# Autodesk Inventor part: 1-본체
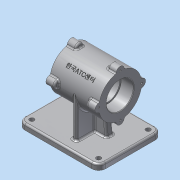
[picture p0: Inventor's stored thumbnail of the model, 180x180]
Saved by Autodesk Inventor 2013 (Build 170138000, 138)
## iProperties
Created: 2015-12
Part Number: 1-본체
Material: 알루미늄 6061
Document SubType Name: Modeling
Designer: ST1
Density: 2.71 g/cm^3
Mass: 1167.31 g
Surface Area: 816.82 cm^2
Volume: 430.742 cm^3
Author: ST1
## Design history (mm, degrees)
sketch "스케치1"
  geometry: L1 (0, 0)-(85, 0); L2 (0, 23.5)-(22, 23.5); L3 (22, 23.5)-(22, 21); L4 (22, 21)-(63, 21); L5 (63, 21)-(63, 23.5); L6 (63, 23.5)-(85, 23.5); L7 (0, 23.5)-(0, 37); L8 (0, 37)-(85, 37); L9 (85, 37)-(85, 23.5)
  constraints: 18 end point, 6 perpendicular, 2 parallel, 2 vertical alignment, 1 horizontal, 1 horizontal alignment
  dimensions: "d0" = 85 distance of L1.start L1.end; "d1" = 47 diameter of L2 L1; "d2" = 22 distance of L2.start L2.end; "d3" = 42 diameter of L4 L1; "d4" = 41 distance of L3.end L4.end; "d5" = 74 diameter of L8 L1
revolve "회전1" sketch "스케치1" stored, may be unused: angle "d6" = 90 deg
sketch "스케치2"
  geometry: C1 r 23.5 at (0, 0) reference; C2 r 7 at (0, 37); C3 r 7 at (37, 0); C4 r 7 at (-37, 0); C5 r 7 at (0, -37); A1 r 37 centre (0, 0) between (0, 37) and (37, 0) reference
  constraints: 4 centre point, 4 point on circle, 3 equal radius, 2 horizontal alignment, 2 vertical alignment
  dimensions: "d7" = 14 diameter of C2
extrude "돌출1" join sketch "스케치2" distance "d9" = 15; taper "d10" = 0 deg
node "작업 평면1"
sketch "스케치3"
  geometry: A1 r 7 centre (0, 0) between (-0.662, -6.969) and (-0.662, 6.969) reference; A2 r 7 centre (-37, 37) between (-30.031, 36.338) and (-43.969, 36.338) reference; A3 r 7 centre (-74, 0) between (-73.338, 6.969) and (-73.338, -6.969) reference; A4 r 7 centre (-37, -37) between (-43.969, -36.338) and (-30.031, -36.338) reference; 4 further points
  constraints: 4 coincident
hole "구멍1" sketch "스케치3" at (-37, 37), (0, 0), (-74, 0), (-37, -37) diameter "d11" = 3.242; stored, may be unused: countersink angle "d15" = 90 deg, drill point angle "d17" = 118 deg; dims "d12" = 9, "d13" = 4, "d14" = 2, "d16" = 11
fillet "모깎기1" dims "d18" = 0.3
chamfer "모따기1" distance "d19" = 1; stored, may be unused: second distance "d20" = 2, angle "d21" = 45 deg
fillet "모깎기2" dims "d22" = 3
sketch "스케치4"
  geometry: L1 (-37, 0)-(-79.773, 42.773); L2 (-37, 0)-(-99.297, 0); C1 r 1.621 at (-37, -37) reference; C2 r 1.621 at (0, 0) reference; C3 r 1.621 at (-37, 37) reference; C4 r 1.621 at (-74, 0) reference; C5 r 24.5 at (-37, 0) reference; A1 r 3 centre (-75.77, -9.842) between (-72.862, -9.104) and (-75.239, -6.889) reference; A2 r 7 centre (-74, 0) between (-75.239, 6.889) and (-75.239, -6.889) reference; A3 r 3 centre (-75.77, 9.842) between (-75.239, 6.889) and (-72.862, 9.104) reference; A4 r 37 centre (-37, 0) between (-46.104, 35.862) and (-72.862, 9.104) reference; A5 r 3 centre (-46.842, 38.77) between (-46.104, 35.862) and (-43.889, 38.239) reference; A6 r 7 centre (-37, 37) between (-30.111, 38.239) and (-43.889, 38.239) reference; A7 r 3 centre (-27.158, 38.77) between (-30.111, 38.239) and (-27.896, 35.862) reference; A8 r 37 centre (-37, 0) between (-1.138, 9.104) and (-27.896, 35.862) reference; A9 r 3 centre (1.77, 9.842) between (-1.138, 9.104) and (1.239, 6.889) reference; A10 r 7 centre (0, 0) between (1.239, -6.889) and (1.239, 6.889) reference; A11 r 3 centre (1.77, -9.842) between (1.239, -6.889) and (-1.138, -9.104) reference; A12 r 37 centre (-37, 0) between (-27.896, -35.862) and (-1.138, -9.104) reference; A13 r 3 centre (-27.158, -38.77) between (-27.896, -35.862) and (-30.111, -38.239) reference; A14 r 7 centre (-37, -37) between (-43.889, -38.239) and (-30.111, -38.239) reference; A15 r 3 centre (-46.842, -38.77) between (-43.889, -38.239) and (-46.104, -35.862) reference; A16 r 37 centre (-37, 0) between (-72.862, -9.104) and (-46.104, -35.862) reference; 1 further point
  constraints: 4 end point, 1 horizontal
  dimensions: "d23" = 45 deg angle of L2 L1
  node "투영된 루프1"
node "작업 평면2"
sketch "스케치5"
  geometry: L1 (-42.5, 18.921)-(-42.5, -18.921) reference; 2 further points
  constraints: 1 horizontal alignment, 1 other
  dimensions: "d24" = 42.5 distance from line of point (0, 0) L1
feature "엠보싱1" sketch "스케치5" dims "d0" = 85, "d1" = 47, "d2" = 22, "d3" = 42, "d4" = 41, "d5" = 74, "d25" = 0.5, "d26" = 0
node "작업 평면3"
sketch "스케치6"
  geometry: L1 (-17.5, 55)-(122.5, 55); L2 (122.5, 55)-(122.5, -55); L3 (122.5, -55)-(-17.5, -55); L4 (-17.5, -55)-(-17.5, 55); L5 (18, 37)-(67, 37) reference; L6 (0, 9.104)-(0, 35.862) reference; 3 further points
  constraints: 8 end point, 2 midpoint, 2 parallel, 1 horizontal, 1 horizontal alignment, 1 perpendicular
  dimensions: "d28" = 110 distance of L1.end L2.end; "d30" = 140 distance of L1.start L1.end; "d46" = 80 distance from line of L2 point (42.5, 37)
extrude "돌출2" join sketch "스케치6" distance "d31" = 10; taper "d32" = 0 deg
fillet "모깎기3" dims "d33" = 12
sketch "스케치7"
  geometry: C1 r 4 at (-5.5, 43); C2 r 4 at (110.5, 43); C3 r 4 at (110.5, -43); C4 r 4 at (-5.5, -43); A1 r 12 centre (110.5, -43) between (110.5, -55) and (122.5, -43) reference; A2 r 12 centre (110.5, 43) between (122.5, 43) and (110.5, 55) reference; A3 r 12 centre (-5.5, 43) between (-5.5, 55) and (-17.5, 43) reference; A4 r 12 centre (-5.5, -43) between (-17.5, -43) and (-5.5, -55) reference; 1 further point
  constraints: 4 centre point, 4 coincident, 3 equal radius
  dimensions: "d34" = 8 diameter of C1
extrude "돌출3" cut sketch "스케치7" distance "d36" = 10; taper "d37" = 0 deg
sketch "스케치8"
  geometry: L1 (122.5, -43)-(122.5, 43) reference; L2 (-5.5, -55)-(110.5, -55) reference; L3 (56.5, -37)-(48.5, -37); L4 (48.5, -37)-(48.5, 37); L5 (48.5, 37)-(56.5, 37); L6 (56.5, 37)-(56.5, -37); 5 further points
  constraints: 8 end point, 4 midpoint, 2 parallel, 1 horizontal, 1 horizontal alignment, 1 perpendicular, 1 vertical alignment
  dimensions: "d38" = 8 distance of L3.start L3.end; "d41" = 74 distance of L3.end L4.end
extrude "돌출4" join sketch "스케치8" stored distance "d42" = 10; taper "d43" = 0 deg
sketch "스케치9"
  geometry: L1 (0, 74)-(70, 74) reference; L2 (0, 0)-(0, 74) reference; L3 (0, 0)-(70, 0) reference; A1 r 37 centre (70, 37) between (70, 74) and (70, 0) reference
sketch "스케치10"
  geometry: L1 (0, 0)-(-70, 0) reference; L2 (0, 74)-(0, 0) reference; L3 (0, 74)-(-70, 74) reference; A1 r 37 centre (-70, 37) between (-70, 0) and (-70, 74) reference
extrude "돌출6" cut sketch "스케치10" distance "d49" = 10; taper "d50" = 0 deg
extrude "돌출9" join sketch "스케치9" distance "d64" = 8; taper "d65" = 0 deg
sketch "스케치14"
  geometry: L1 (70, 74)-(0, 74) reference; L2 (0, 0)-(0, 74) reference; L3 (0, 0)-(70, 0) reference; A1 r 37 centre (70, 37) between (70, 74) and (70, 0) reference
extrude "돌출10" join sketch "스케치14" distance "d66" = 2; taper "d67" = 0 deg
sketch "스케치15"
  geometry: L1 (0, 0)-(-70, 0) reference; L2 (0, 74)-(0, 0) reference; L3 (-70, 74)-(0, 74) reference; A1 r 37 centre (-70, 37) between (-70, 0) and (-70, 74) reference
extrude "돌출11" cut sketch "스케치15" distance "d68" = 2; taper "d69" = 0 deg
sketch "스케치16"
  geometry: L1 (46.5, -37)-(38.5, -37) reference; L2 (67.5, -6)-(17.5, -6); L3 (17.5, -6)-(17.5, 6); L4 (17.5, 6)-(67.5, 6); L5 (67.5, 6)-(67.5, -6); 4 further points
  constraints: 8 end point, 3 midpoint, 2 parallel, 1 horizontal, 1 horizontal alignment, 1 perpendicular, 1 vertical alignment
  dimensions: "d70" = 50 distance of L2.start L2.end; "d72" = 12 distance of L2.end L3.end
extrude "돌출12" join sketch "스케치16" stored distance "d73" = 2; taper "d74" = 0 deg
sketch "스케치17"
  geometry: L1 (21, -33.49)-(0, -33.49) reference; L2 (0, 0)-(0, -33.49) reference; L3 (29, -33.49)-(50, -33.49) reference; L4 (29, 0)-(29, -33.49) reference; L5 (50, 0)-(29, 0) reference; L6 (50, 0)-(50, -33.49) reference; L7 (50, 0)-(45.888, -33.49); L8 (0, 0)-(4.112, -33.49); L9 (-23, 0)-(93, 0) reference; 1 further point
  constraints: 4 end point, 2 point on line
  dimensions: "d75" = 97 deg angle of L5 L7; "d76" = 97 deg angle of L9 L8
extrude "돌출13" cut sketch "스케치17" stored distance "d77" = 2; taper "d78" = 0 deg
fillet "모깎기4" dims "d79" = 3
fillet "모깎기5" dims "d80" = 3
node "솔리드1"
mirror "대칭1"
mirror "대칭2"
node "투영된 루프6"
